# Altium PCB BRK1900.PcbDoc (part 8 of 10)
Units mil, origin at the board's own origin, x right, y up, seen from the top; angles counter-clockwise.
Board outline 8858.27 x 5905.51 mil, 10 copper layers (L1-TOP, L2-GND, L3-SIG1, L4-GND, L5-PWR, L6-PWR, L7-GND, L8-SIG2, L9-GND, L10-BOT), stack 48.824 mil thick; 507 components, 607 nets, 2498 pads, 2210 vias.
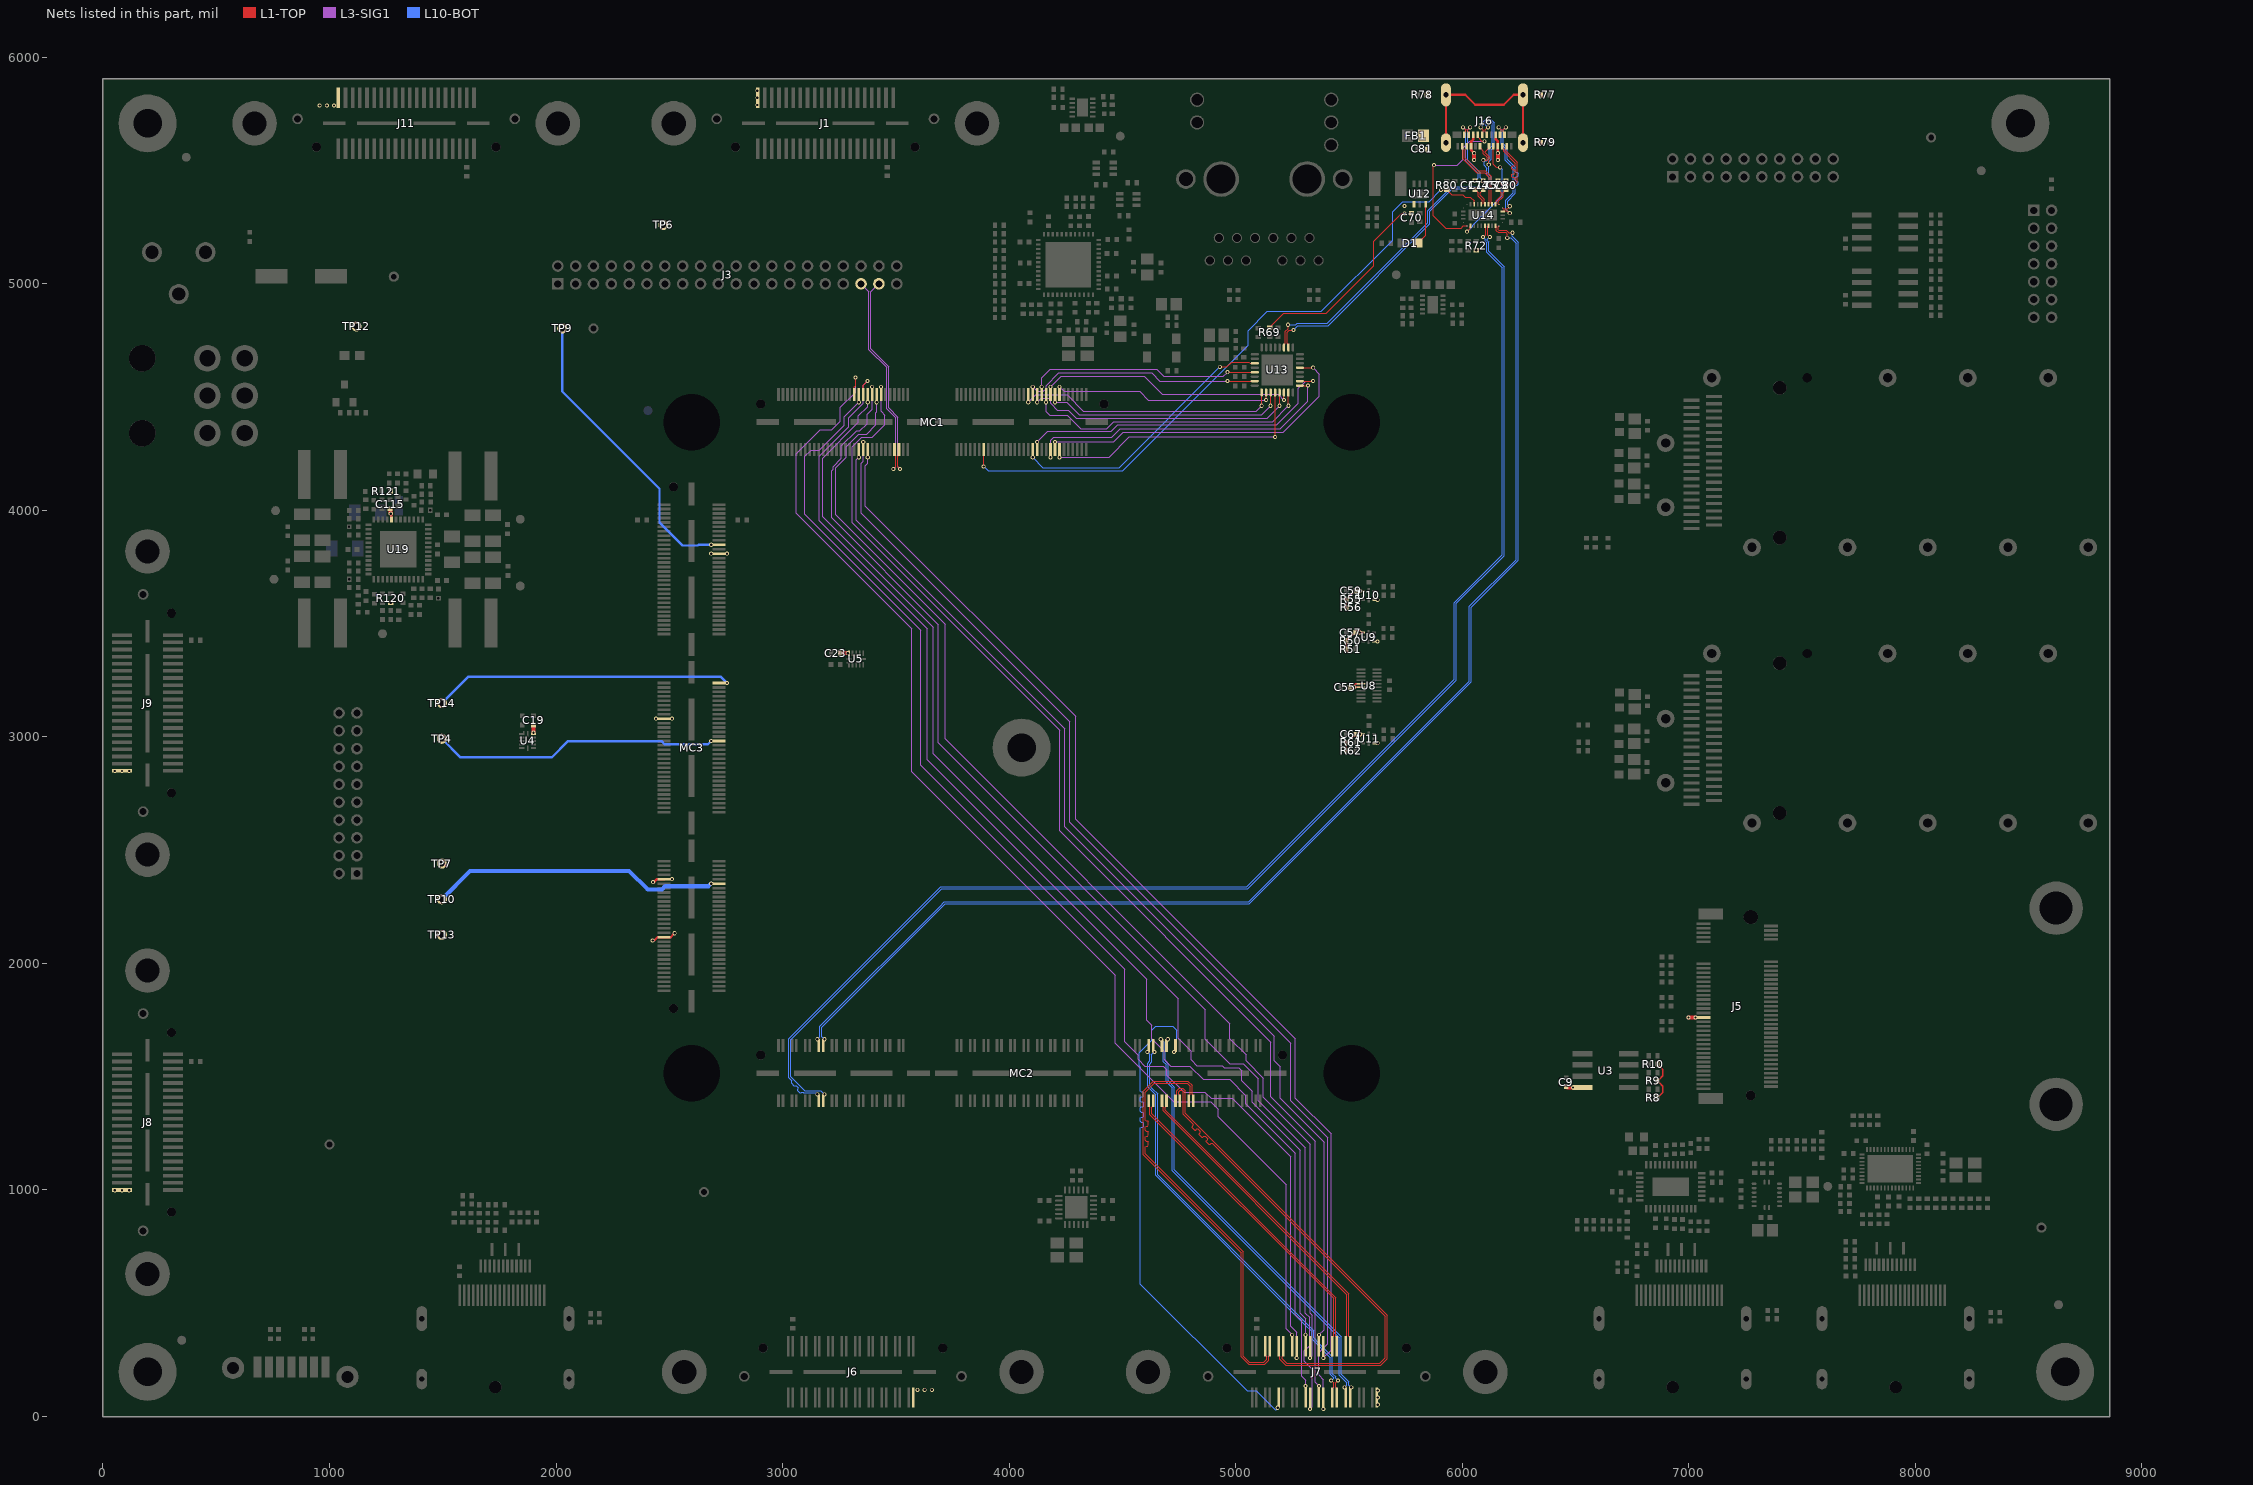
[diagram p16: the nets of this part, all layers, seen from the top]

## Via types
v1: diameter 18, hole 10, L1-TOP to L10-BOT, tented both sides, 2210 vias

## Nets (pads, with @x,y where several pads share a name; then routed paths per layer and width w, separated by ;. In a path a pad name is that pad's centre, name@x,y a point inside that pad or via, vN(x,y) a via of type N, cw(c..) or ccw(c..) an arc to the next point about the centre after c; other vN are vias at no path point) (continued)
SZG_PORTF_RX1P: J7.9 MC2.93 | length 2286.4
  L10-BOT w3.3: v1(4728.35,1609.4) 4739.59,1620.65 4739.59,1704.41 4722,1722 4646.56,1722 4630.06,1705.5 4630.06,1659.94 4575,1604.88 4575,1547.73 4580,1542.73 4580,1443 4580,1436.74 4583.35,1433.4 4589.27,1433.4 4592.61,1430.05 4592.61,1414.44 4589.27,1411.1 4583.35,1411.1 4580,1407.75 4580,1392.14 4583.35,1388.8 4590.66,1388.8 4594,1385.45 4594,1369.84 4590.66,1366.5 4583.35,1366.5 4580,1363.15 4580,1347.54 4583.35,1344.2 4590.66,1344.2 4594,1340.85 4594,1325.24 4590.66,1321.9 4583.35,1321.9 4580,1318.55 4580,1302.94 4583.35,1299.6 4590.66,1299.6 4594,1296.25 4594,1280.64 4590.66,1277.3 4583.35,1277.3 4580,1273.95 4580,1250 4580,584 5051,113 5092,113 5174,31 5178.71,31 v1@5186.56,38.86
  other v1: 5185.46,38.86
SZG_PORTF_RX2N: J7.31 MC2.91 | length 1880.8
  L10-BOT w3.3: v1(4700.79,1665.4) 4689.54,1654.15 4689.54,1570.46 4702,1558 4702,1482 4730,1454 4730,1089 5467,352 5467,185.85 5500.12,152.73 5500.12,138.14 v1@5509.4,128.86
  other v1: 5510.5,128.86
SZG_PORTF_RX2P: J7.29 MC2.89 | length 1880.8
  L10-BOT w3.3: v1(4669.29,1665.4) 4680.54,1654.15 4680.54,1566.73 4693,1554.27 4693,1478.27 4721,1450.27 4721,1085.27 5458,348.27 5458,182.12 5491.12,149 5491.12,138.14 v1@5481.84,128.86
  other v1: 5480.74,128.86
SZG_PORTF_RX3N: J7.27 MC2.87 | length 1884.5
  L1-TOP w3.3: J7.27@5446.41,83.86 5446.41,123.22 5441.06,128.57 5441.06,149.58 v1@5450.34,158.86
  L10-BOT w3.3: v1(4641.73,1609.4) 4630.48,1598.15 4630.48,1566.27 4620,1555.79 4620,1460 4633,1447 4656,1424 4656,1067.73 5306.73,417 5344,379.73 5344,347 5363,328 5427,264 5427,189.79 5441.06,175.73 5441.06,168.14 v1@5450.34,158.86
  other v1: 5451.44,158.86
SZG_PORTF_RX3P: J7.25 MC2.85 | length 1884.5
  L1-TOP w3.3: v1@5422.78,158.86 5432.06,149.58 5432.06,128.43 5426.72,123.09 J7.25@5426.72,83.86
  L10-BOT w3.3: v1(4610.24,1609.4) 4621.48,1598.15 4621.48,1570 4611,1559.52 4611,1456.27 4647,1420.27 4647,1064 5303,408 5335,376 5335,343.27 5418,260.27 5418,186.06 5432.06,172 5432.06,168.14 v1@5422.78,158.86
  other v1: 5421.68,158.86
SZG_PORTF_S0: J7.14 MC1.35 | length 5444.4
  L1-TOP w4.55: MC1.35@3316.93,4511.42 3316.93,4544.93 3322.07,4550.07 v1(3322.07,4586.36)
  L3-SIG1 w4.05: v1(3322.07,4586.36) 3322.07,4522.07 3254.64,4454.64 3254.64,4392.64 3217.54,4355.54 3165.92,4355.54 3060,4249.62 3060,3987 3570.5,3476.5 3570.5,2846.82 4468.5,1948.82 4468.5,1648.47 4726.98,1390 4891,1390 4924,1357 4924,1323.68 5224,1023.68 5224,386.4 v1(5249.56,360.84)
SZG_PORTF_S1: J7.16 MC1.37 | length 5393.9
  L3-SIG1 w4.05: v1(3336.61,4477.42) 3272,4412.8 3272,4375.72 3162.28,4266 3126,4266 3099,4239 3099,3983 3611,3471 3611,2874 4510.5,1974.5 4510.5,1653.5 4569.5,1594.5 4569.5,1576.5 4599,1547 4681,1547 4697,1531 4697,1507.5 4772.5,1432 4864,1432 4892,1404 4986,1404 5244,1146 5244,398.01 5269.24,372.77 v1(5269.24,258.84)
SZG_PORTF_S2: J7.17 MC1.39 | length 5599.6
  L1-TOP w4.55: MC1.39@3356.3,4511.42 3356.3,4552.63 v1(3375.31,4571.65)
  L3-SIG1 w4.05: v1(3375.31,4571.65) 3356.3,4552.63 3356.3,4472.3 3292,4408 3292,4369 3162,4239 3162,3954 3638.5,3477.5 3638.5,2899.5 4607,1931 4607,1749 4629,1727 4629,1668 4684,1613 4684,1577 4714,1547 4797,1547 4856,1488 4973,1488 5045,1416 5045,1381 5264,1162 5264,449 5291,422 5291,178 5308.61,160.39 v1(5308.61,134.86)
SZG_PORTF_S3: J7.18 MC1.41 | length 5185
  L3-SIG1 w4.05: v1(3375.98,4477.42) 3375.98,4457.98 3335,4417 3335,4388 3177,4230 3177,3973 3666,3484 3666,2925 4747,1844 4747,1670 4804,1613 4804,1574 4829,1549 4941,1549 4950,1540 5014,1540 5028,1526 5028,1483 5074,1437 5074,1388 5286,1176 5286,455 5308.61,432.39 v1(5308.61,360.84)
SZG_PORTF_S4: J7.19 MC1.43 | length 5532.5
  L3-SIG1 w4.05: v1(3395.67,4545.42) 3395.67,4446.67 3373,4424 3373,4383 3341,4351 3326.58,4351 3260,4284.42 3260,4229.08 3224,4193.08 3224,4181 3217,4174 3217,3967 3688,3496 3688,2974 4866,1796 4866,1665 4973,1558 5034,1558 5100,1492 5100,1395 5308,1187 5308,456 5326.17,437.83 5326.17,313.17 5303,290 5303,243 5338,208 5338,42.56 v1(5328.3,32.86)
SZG_PORTF_S5: J7.20 MC1.45 | length 5190.1
  L3-SIG1 w4.05: v1(3415.35,4477.42) 3415.35,4435.35 3412,4432 3412,4378 3371,4337 3336.23,4337 3281,4281.77 3281,4235.3 3234,4188.3 3234,3981 3718,3497 3718,2991 4975,1734 4975,1667 5046,1596 5046,1570 5122,1494 5122,1410 5330,1202 5330,455 5338.58,446.42 5338.58,269.12 v1(5328.3,258.84)
SZG_PORTF_S6: J7.21 MC1.47 | length 5358.7
  L3-SIG1 w4.05: v1(3435.04,4545.42) 3435.04,4436.96 3452,4420 3452,4379 3396,4323 3349.06,4323 3307,4280.94 3307,3945 4223,3029 4223,2585 5155,1653 5155,1550 5155,1412 5351,1216 5351,151.53 v1(5367.67,134.86)
SZG_PORTF_S7: J7.22 MC1.38 | length 4742.7
  L3-SIG1 w4.05: v1(3336.61,4234.11) 3326,4223.5 3326,3957 4246,3037 4246,2603 5170,1679 5170,1571 5196,1545 5196,1405 5391,1210 5391,384.18 v1(5367.67,360.84)
SZG_PORTF_S8: J7.23 MC1.40 | length 5151.4
  L3-SIG1 w4.05: v1(3356.3,4302.11) 3356.3,4216.3 3347,4207 3347,3988 4267,3068 4267,2623 5243,1647 5243,1394 5406,1231 5406,321 5366,281 5366,184 5387.35,162.65 v1(5387.35,32.86)
SZG_PORTF_S9: J7.24 MC1.42 | length 4844.5
  L3-SIG1 w4.05: v1(3375.98,4234.11) 3375.98,4206.98 3366,4197 3366,4019 4293.5,3091.5 4293.5,2636.5 5263,1667 5263,1406 5421,1248 5421,292.49 v1(5387.35,258.84)
SZG_PORTF_TX0N: J7.8 MC2.100 | length 1867.5
  L1-TOP w3.3: MC2.100@4812.99,1394.09 4812.99,1417.03 4807.65,1422.37 4807.65,1432.73 4807.65,1461.54 4789.5,1479.69 4635.96,1479.69 4610.06,1453.78 4592,1435.73 4592,1156 5025,723 5025,263.27 5057.27,231 5127.73,231 5145.79,249.06 5145.79,265.14 5151.13,270.48 J7.8@5151.13,309.84
SZG_PORTF_TX0P: J7.6 MC2.98 | length 1867.5
  L1-TOP w3.3: MC2.98@4793.31,1394.09 4793.31,1416.67 4798.65,1422.01 4798.65,1457.81 4785.77,1470.69 4639.69,1470.69 4601,1432 4601,1326 4601,1308 4604.35,1304.66 4611.24,1304.66 4614.58,1301.31 4614.58,1285.7 4611.24,1282.36 4604.35,1282.36 4601,1279.01 4601,1263.4 4604.35,1260.06 4611.66,1260.06 4615,1256.71 4615,1241.1 4611.66,1237.76 4604.35,1237.76 4601,1234.41 4601,1218.8 4604.35,1215.46 4611.66,1215.46 4615,1212.11 4615,1196.5 4611.66,1193.16 4604.35,1193.16 4601,1189.81 4601,1165.86 4601,1159.73 5034,726.73 5034,267 5061,240 5124,240 5136.79,252.79 5136.79,264.74 5131.45,270.09 J7.6@5131.45,309.84
SZG_PORTF_TX1N: J7.12 MC2.96 | length 2202.8
  L1-TOP w3.3: MC2.96@4753.94,1394.09 4753.94,1416.88 4748.59,1422.22 4748.59,1434.59 4755,1441 4763,1441 4769,1435 4769,1334 4796,1307 4812.94,1290.06 4812.94,1285.33 4807.77,1280.17 4807.77,1275.43 4818.8,1264.4 4823.54,1264.4 4828.7,1269.57 4833.43,1269.57 4844.47,1258.53 4844.47,1253.8 4839.3,1248.63 4839.3,1243.9 4850.34,1232.86 4855.07,1232.86 4860.24,1238.03 4864.97,1238.03 4876.01,1226.99 4876.01,1222.26 4871.14,1217.39 4871.14,1212.66 4882.18,1201.62 4886.91,1201.62 4891.78,1206.49 4896.51,1206.49 4905,1198 5660,443 5660,259 5636,235 5225.84,235 5204.84,256 5204.84,264.72 5210.19,270.06 J7.12@5210.19,309.84
SZG_PORTF_TX1P: J7.10 MC2.94 | length 2202.8
  L1-TOP w3.3: MC2.94@4734.25,1394.09 4734.25,1416.66 4739.59,1422 4739.59,1438.32 4751.27,1450 4766.73,1450 4778,1438.73 4778,1337.73 5669,446.73 5669,255.27 5639.73,226 5222.12,226 5195.84,252.27 5195.84,265.46 5190.5,270.8 J7.10@5190.5,309.84
SZG_PORTF_TX2N: J7.32 MC2.92 | length 1424.4
  L1-TOP w3.3: MC2.92@4694.88,1394.09 4694.88,1371.18 4689.54,1365.84 4689.54,1352.46 4714,1328 5500.12,541.88 5500.12,354.26 5505.46,348.92 J7.32@5505.46,309.84
SZG_PORTF_TX2P: J7.30 MC2.90 | length 1424.4
  L1-TOP w3.3: MC2.90@4675.2,1394.09 4675.2,1371.09 4680.54,1365.75 4680.54,1348.73 5491.12,538.15 5491.12,354.2 5485.78,348.86 J7.30@5485.78,309.84
SZG_PORTF_TX3N: J7.28 MC2.88 | length 1424.4
  L1-TOP w3.3: MC2.88@4635.83,1394.09 4635.83,1371.34 4630.48,1366 4630.48,1335.52 5441.06,524.94 5441.06,354.03 5446.41,348.69 J7.28@5446.41,309.84
SZG_PORTF_TX3P: J7.26 MC2.86 | length 1424.4
  L1-TOP w3.3: MC2.86@4616.14,1394.09 4616.14,1371.26 4621.48,1365.91 4621.48,1331.79 5432.06,521.21 5432.06,354.59 5426.72,349.25 J7.26@5426.72,309.84
USB_CC1: J16.A5 U14.2 | length 509.1
  L1-TOP w5: v1(6021.41,5230.32) 6035.82,5244.74 6035.82,5254.56 U14.2@6037.26,5256 ; J16.A5@6137.8,5607.09 6137.8,5528.7 6148.6,5517.9 6152.25,5514.25 v1(6167.86,5514.25)
  L10-BOT w5: v1(6021.41,5230.32) 6046,5254.91 6046,5259 6176,5389 6176,5505.58 6168.03,5513.55 6163.68,5517.9 6167.33,5514.25 v1(6167.86,5514.25)
USB_CC2: J16.B5 U14.1 | length 743.3
  L1-TOP w5: v1(5876,5524) 5872.61,5520.61 5872.61,5300.39 5927.01,5245.99 5995.08,5245.99 6005.09,5256 U14.1@6021.51,5256 ; J16.B5@6068.9,5658.27 6068.9,5648.32 6087.37,5629.85 6097.71,5629.85 v1(6098.46,5629.1)
  L3-SIG1 w5: v1(5876,5524) 5979,5524 6003,5548 6003,5598 6034.1,5629.1 v1(6098.46,5629.1)
USB_CLKOUT: MC1.93 U13.1 | length 1142.6
  L1-TOP w4.55: v1(5115.05,4461.87) U13.1@5115.05,4520.65
  L3-SIG1 w4.05: v1(4084.65,4477.42) 4117.15,4509.92 4256.08,4509.92 4328.29,4437.71 5090.89,4437.71 v1(5115.05,4461.87)
USB_DATA0: MC1.105 U13.3 | length 1049.5
  L1-TOP w4.55: v1(5154.41,4461.87) U13.3@5154.42,4520.65
  L3-SIG1 w4.05: v1(4202.76,4477.42) 4254.58,4477.42 4309.53,4422.47 5115.01,4422.47 v1(5154.41,4461.87)
USB_DATA1: MC1.108 U13.4 | length 1185.9
  L1-TOP w4.55: U13.4@5174.1,4520.65 5174.1,4324.68 v1(5174.47,4324.31)
  L3-SIG1 w4.05: v1(4222.44,4234.11) 4441.11,4234.11 4531.31,4324.31 v1(5174.47,4324.31)
USB_DATA2: MC1.97 U13.5 | length 1202.4
  L1-TOP w4.55: v1(5193.79,4461.87) U13.5@5193.79,4520.65
  L3-SIG1 w4.05: v1(4124.02,4477.42) 4141.4,4494.8 4174.76,4494.8 4183,4486.56 4183,4472.64 4212.64,4443 4261,4443 4296.3,4407.7 5139.62,4407.7 v1(5193.79,4461.87)
USB_DATA3: MC1.103 U13.6 | length 1127
  L1-TOP w4.55: v1(5213.47,4486.87) U13.6@5213.47,4520.65
  L3-SIG1 w4.05: v1(4183.07,4545.42) 4229.65,4592 4597,4592 4677,4512 5188.34,4512 v1(5213.47,4486.87)
USB_DATA4: MC1.101 U13.7 | length 1244.5
  L1-TOP w4.55: v1(5233.16,4461.87) U13.7@5233.16,4520.65
  L3-SIG1 w4.05: v1(4163.39,4477.42) 4163.39,4434.6 4178.99,4419 4257,4419 4316,4360 4431,4360 4463,4392 5163.29,4392 v1(5233.16,4461.87)
USB_DATA5: MC1.104 U13.9 | length 1388.3
  L1-TOP w4.55: U13.9@5283.35,4551.16 5318.57,4551.16 v1(5319.13,4551.72)
  L3-SIG1 w4.05: v1(4183.07,4234.11) 4183.07,4309.07 4196.43,4322.43 4453,4322.43 4491.57,4361 5198,4361 5319.13,4482.13 v1(5319.13,4551.72)
USB_DATA6: MC1.98 U13.10 | length 1427.5
  L1-TOP w4.55: U13.10@5283.35,4570.84 v1(5342.13,4570.84)
  L3-SIG1 w4.05: v1(4124.02,4302.11) 4170.9,4349 4451,4349 4479,4377 5182,4377 5277,4472 5277,4539 5308.84,4570.84 v1(5342.13,4570.84)
USB_DATA7: MC1.106 U13.13 | length 1447.2
  L1-TOP w4.55: U13.13@5283.35,4629.9 v1(5342.13,4629.9)
  L3-SIG1 w4.05: v1(4202.76,4302.11) 4463,4302.11 4504.89,4344 5210.14,4344 5370.08,4503.94 5370.08,4601.95 v1(5342.13,4629.9)
USB_DIR: MC1.95 U13.31 | length 1043.8
  L1-TOP w4.55: v1(4964.54,4570.84) U13.31@5084.54,4570.84
  L3-SIG1 w4.05: v1(4104.33,4545.42) 4123.75,4526 4151,4526 4163,4538 4163,4550 4220,4607 4629,4607 4665.16,4570.84 v1(4964.54,4570.84)
USB_DN: J16.A7 J16.B7 U13.19 | length 1777.1
  L1-TOP w4.05: U13.19@5213.47,4719.46 5213.47,4731.27 5218.81,4736.61 5218.81,4789.8 5231.38,4802.36 v1(5231.38,4819.62) ; J16.A7@6078.74,5607.09 6078.74,5599.99 6093.93,5584.81 6093.93,5574.08 6108,5560 6111.51,5556.49 6111.51,5548.49 6109.11,5546.1 v1(6093.48,5546.1) ; J16.B7@6108.27,5658.27 6108.27,5666.12 6102.93,5671.46 6102.93,5679.55 v1(6114.41,5691.04)
  L10-BOT w4.05: v1(5231.38,4819.62) 5265.59,4819.62 5270.97,4825 5405,4825 5849,5269 5849,5307.08 5849,5323.45 5953.55,5428 6106,5428 6120,5442 6120,5469.33 6108.48,5480.86 6108.48,5510.79 6096.48,5522.79 6096.48,5543.1 6109.11,5543.1 6119.5,5553.49 6119.5,5596.5 6133,5610 6133,5708 6123.52,5717.48 6108.95,5717.48 6102.48,5711 6102.48,5702.98 v1(6114.41,5691.04)
USB_DP: J16.A6 J16.B6 U13.18 | length 1784.5
  L1-TOP w4.05: U13.18@5233.16,4719.46 5233.16,4731.49 5227.81,4736.83 5227.81,4786.07 5237.74,4796 v1(5255,4796) ; v1(6081.54,5691.04) 6093.93,5678.66 6093.93,5671.26 6088.58,5665.91 J16.B6@6088.58,5658.27 ; v1(6117.48,5526.1) 6117.48,5541.74 6117.87,5542.13 6120.51,5544.77 6120.51,5560.22 6117.87,5562.86 6102.93,5577.8 6102.93,5584.15 6118.11,5599.33 J16.A6@6118.11,5607.09
  L10-BOT w4.05: v1(5255,4796) 5275,4816 5408.73,4816 5858,5265.27 5858,5319.72 5957.28,5419 6109.73,5419 6112.36,5421.64 6129,5438.27 6129,5473.06 6117.48,5484.58 v1(6117.48,5526.1) 6117.48,5538.74 6128.5,5549.76 6128.5,5592.77 6142,5606.27 6142,5711.73 6127.25,5726.48 6105.23,5726.48 6093.48,5714.73 6093.48,5702.98 v1(6081.54,5691.04)
USB_NXT: MC1.107 U13.2 | length 970.3
  L1-TOP w4.55: v1(5134.73,4486.87) U13.2@5134.73,4520.65
  L3-SIG1 w4.05: v1(4222.44,4545.42) 4242.86,4525 4279.98,4525 4577,4525 4615.13,4486.87 v1(5134.73,4486.87)
USB_RESET_B: MC1.96 U13.27 | length 1194.2
  L1-TOP w4.55: v1(4930.11,4633.87) 4961.87,4633.87 4983,4655 5059,4655 5064.42,4649.58 U13.27@5084.54,4649.58
  L10-BOT w4.55: v1(4104.33,4234.11) 4149.44,4189 4485.23,4189 v1(4930.11,4633.87)
USB_SHELL: C81.2 FB1.1 J16.M1 J16.M2 J16.M3 J16.M4 R77.1 R78.1 R79.1 | length 798.8
  L1-TOP w10: J16.M2@5928.35,5623.23 J16.M3@5928.35,5834.25 6013.08,5834.25 6057.23,5790.1 6183.55,5790.1 6227.7,5834.25 J16.M4@6268.5,5834.25 J16.M1@6268.5,5623.23
USB_SSRX_N: MC2.15 U14.10 | length 5720.4
  L1-TOP w4.05: U14.10@6163.24,5256 6159.87,5252.63 6159.87,5239 6162.87,5236 6195.05,5236 6203.02,5228.02 6205.36,5225.68 v1(6221.69,5225.68)
  L10-BOT w4.05: v1(3185.04,1665.4) 3173.79,1676.65 3173.79,1719 3718.57,2263.78 5060.84,2263.78 6040,3242.94 6040,3572.27 6247,3779.27 6247,5184.05 6221.69,5209.36 v1(6221.69,5225.68)
USB_SSRX_P: MC2.13 U14.9 | length 5720.4
  L1-TOP w4.05: U14.9@6147.5,5256 6150.87,5252.63 6150.87,5235.27 6159.14,5227 6191.32,5227 6199,5219.32 v1(6199,5203)
  L10-BOT w4.05: v1(3153.54,1665.4) 3164.79,1676.65 3164.79,1722.73 3695.06,2253 3714.84,2272.78 5057.11,2272.78 6031,3246.67 6031,3576 6238,3783 6238,5180.32 6215.32,5203 v1(6199,5203)
USB_SSRXN1: J16.B10 U14.14 | length 503.9
  L1-TOP w4.05: v1(6161.02,5691.04) 6172.67,5679.4 6172.67,5671.67 6167.32,5666.33 J16.B10@6167.32,5658.27 ; U14.14@6178.99,5318.99 6182.37,5322.37 6199.77,5322.37 v1(6210.05,5312.09)
  L10-BOT w4.05: v1(6161.02,5691.04) 6172.46,5679.6 6172.46,5615.81 6190.64,5597.64 6190.64,5546.36 6226,5511 6226,5402.73 6192,5368.73 6192,5330.14 v1(6210.05,5312.09)
USB_SSRXN2: J16.A10 U14.18 | length 327.7
  L1-TOP w4.05: J16.A10@6019.69,5607.09 6019.69,5598.83 6014.34,5593.49 6014.34,5553.66 6067.96,5500.04 6102.52,5500.04 6128.37,5474.19 6128.37,5353.86 U14.18@6131.75,5350.49
USB_SSRXP1: J16.B11 U14.15 | length 501.8
  L1-TOP w4.05: U14.15@6178.99,5334.74 6182.37,5331.37 6201.76,5331.37 v1@6210.05,5339.65 ; J16.B11@6187.01,5658.27 6187.01,5666.25 6181.67,5671.6 6181.67,5679.81 v1(6192.89,5691.04)
  L10-BOT w4.05: v1(6192.89,5691.04) 6181.46,5679.6 6181.46,5619.54 6197,5604 6199.64,5601.36 6199.64,5550.09 6235,5514.73 6235,5502 6235,5495.85 6238.81,5492.04 6243.19,5492.04 6247,5488.23 6247,5476.8 6243.19,5472.99 6238.81,5472.99 6235,5469.18 6235,5457.75 6238.81,5453.94 6243.19,5453.94 6247,5450.13 6247,5438.7 6243.19,5434.89 6238.81,5434.89 6235,5431.08 6235,5410 6235,5399 6201,5365 6201,5348.69 v1@6210.05,5339.65
  other v1: 6210.05,5342.65
USB_SSRXP2: J16.A11 U14.19 | length 327.7
  L1-TOP w4.05: J16.A11@6000,5607.09 6000,5598.96 6005.34,5593.62 6005.34,5549.93 6055.27,5500 6064.23,5491.04 6098.79,5491.04 6119.37,5470.46 6119.37,5353.86 U14.19@6116,5350.49
USB_SSTX_N: MC2.16 U14.7 | length 6072.5
  L1-TOP w4.05: U14.7@6116,5256 6112.63,5252.63 6112.63,5215.37 v1@6121,5207
  L10-BOT w4.05: v1(3185.04,1422.09) 3169.56,1437.58 3097.42,1437.58 3036,1499 3036,1664 3702,2330 5052.72,2330 5973.98,3251.27 5973.98,3589.26 6185,3800.27 6185,5075 6117,5143 6117,5185.72 6111.72,5191 6111.72,5197.72 v1@6121,5207
  other v1: 6122.1,5207
USB_SSTX_P: MC2.14 U14.6 | length 6072.5
  L1-TOP w4.05: v1@6093.44,5207 6103.63,5217.19 6103.63,5252.63 U14.6@6100.25,5256
  L10-BOT w4.05: v1(3153.54,1422.09) 3147.06,1428.58 3093.7,1428.58 3092.27,1430 3090.84,1431.43 3084.89,1431.43 3082.9,1429.45 3076.95,1429.45 3068.02,1438.38 3068.02,1444.33 3070,1446.32 3070,1452.27 3061.07,1461.2 3055.12,1461.2 3049.16,1461.2 3040.23,1470.13 3040.23,1476.09 3040.23,1482.04 3036.64,1485.64 3027,1495.27 3027,1667.73 3698.27,2339 5048.99,2339 5964.98,3255 5964.98,3592.98 6176,3804 6176,5071.27 6110,5137.27 6108,5139.27 6108,5181.99 6102.72,5187.27 6102.72,5197.72 v1@6093.44,5207
  other v1: 6092.34,5207
USB_SSTXN1: C80.2 J16.A3 | length 270.8
  L1-TOP w4.05: J16.A3@6177.17,5607.09 6177.17,5598.97 6182.51,5593.63 6182.51,5584.49 6234.78,5532.22 6234.78,5524.32 6231.37,5520.91 6223.26,5520.91 6219.85,5517.5 6219.85,5507.27 6223.26,5503.86 6231.37,5503.86 6234.78,5500.45 6234.78,5490.22 6231.37,5486.81 6222.19,5486.81 6218.78,5483.4 6218.78,5473.17 6222.19,5469.76 6231.37,5469.76 6234.78,5466.35 6234.78,5464.33 6234.78,5452.5 6229.29,5447 6202.08,5447 v1(6194,5455.08)
USB_SSTXN1_C: C80.1 U14.16 | length 80
  L1-TOP w4.05: U14.16@6163.24,5350.49 6159.87,5353.86 6159.87,5364 6180.5,5384.63 6180.5,5401.42 C80.1@6194,5414.92
USB_SSTXN2: C175.2 J16.B3 | length 308.9
  L1-TOP w4.05: J16.B3@6029.53,5658.27 6029.53,5666.37 6024.19,5671.71 6024.19,5679.81 v1(6035.41,5691.04)
  L10-BOT w4.05: v1(6035.41,5691.04) 6023.98,5679.6 6023.98,5545.33 6079.5,5489.81 6079.5,5468.58 v1(6093,5455.08)
USB_SSTXN2_C: C175.1 U14.20 | length 78.6
  L1-TOP w4.05: C175.1@6093,5414.92 6079.5,5401.42 6079.5,5390.89 6096.88,5373.51 6096.88,5369.73 6096.88,5353.86 U14.20@6100.25,5350.49
USB_SSTXP1: C79.2 J16.A2 | length 279.5
  L1-TOP w4.05: v1(6158,5455.08) 6175.08,5438 6223.73,5438 6233.02,5438 6243.78,5448.77 6243.78,5458.06 6243.78,5530.94 6243.78,5535.94 6191.51,5588.22 6191.51,5593.39 6196.85,5598.73 J16.A2@6196.85,5607.09
USB_SSTXP1_C: C79.1 U14.17 | length 80
  L1-TOP w4.05: U14.17@6147.5,5350.49 6150.87,5353.86 6150.87,5367.73 6171.5,5388.36 6171.5,5401.42 C79.1@6158,5414.92
USB_SSTXP2: C174.2 J16.B2 | length 309.1
  L1-TOP w4.05: v1(6003.54,5691.04) 6015.19,5679.4 6015.19,5671.84 6009.84,5666.49 J16.B2@6009.84,5658.27
  L10-BOT w4.05: v1(6003.54,5691.04) 6014.98,5679.6 6014.98,5545.29 6014.98,5541.6 6070.5,5486.08 6070.5,5468.58 v1(6057,5455.08)
USB_SSTXP2_R: C174.1 U14.21 | length 78.6
  L1-TOP w4.05: C174.1@6057,5414.92 6070.5,5401.42 6070.5,5387.16 6087.88,5369.78 6087.88,5353.86 U14.21@6084.5,5350.49
USB_STP: MC1.99 U13.29 | length 1015.5
  L1-TOP w4.55: v1(4964.54,4610.21) U13.29@5084.54,4610.21
  L3-SIG1 w4.05: v1(4143.7,4545.42) 4143.7,4584.7 4181,4622 4652.21,4622 4682.21,4592 4946.32,4592 v1(4964.54,4610.21)
USB_TYPEC_INT_B: MC1.74 R80.1 U14.23 | length 2908.4
  L1-TOP w5: v1(3887.79,4194.11) MC1.74@3887.79,4268.11 ; v1(5906.68,5414.4) 5931.64,5414.4 5953.05,5393 6003.25,5393 6013,5383.25 6036.75,5383.25 6053.01,5366.99 U14.23@6053.01,5350.49
  L10-BOT w5: v1(3887.79,4194.11) 3906.91,4175 4502,4175 5055,4728 5055,4793 5140,4878 5378,4878 5693,5193 5693,5318.85 5737.15,5363 5855,5363 5906.4,5414.4 v1(5906.68,5414.4)
USB_VBUS: C70.2 J16.A4 J16.A9 J16.B4 J16.B9 R69.1 R72.2 U12.1 | length 1104.3
  L1-TOP w5: R69.1@5150.41,4805.55 5150.41,4807.41 5213,4870 5399,4870 5609,5080 5609,5187 5733.04,5311.04 v1(5745.54,5311.04)
  L1-TOP w11: J16.B4@6049.21,5658.27 6049.21,5638.48 6039.37,5628.64 J16.A9@6039.37,5607.09 6039.37,5590.55 v1(6052.82,5577.1) ; J16.B9@6147.64,5658.27 6147.64,5638.94 6157.48,5629.1 J16.A4@6157.48,5607.09 v1(6157.48,5577.1)
  L1-TOP w18: v1(6052.82,5547.1) v1(6052.82,5577.1) ; v1(6157.48,5547.1) v1(6157.48,5577.1)
  other v1: 6062.41,5148.64 5777.06,5311.04 5745.23,5343.37
VBUS_FAULT: D1.1 U12.3 | length 186.3
  L1-TOP w5: D1.1@5803.46,5180 5838.59,5215.13 U12.3@5838.59,5351.72
VCC_EEPROM_FPX1301: C9.2 J5.33 R8.2 R9.2 R10.2 U3.8 | length 295.4
  L1-TOP w7: v1(6862.28,1407.15) 6862.28,1409.12 6868.63,1415.46 6870.59,1415.46 6885.6,1430.46 6885.6,1457.83 6870.59,1472.84 6868.63,1472.84 6862.28,1479.18 R9.2@6862.28,1481.15 6862.28,1483.12 6868.63,1489.46 6870.59,1489.46 6885.6,1504.46 6885.6,1531.83 6870.59,1546.84 6868.63,1546.84 6862.28,1553.18 R10.2@6862.28,1555.15
  L1-TOP w18: C9.2@6459.6,1456.07 6460.19,1456.07 6464.11,1452.15 v1(6489.24,1452.15) U3.8@6531.24,1452.15 ; v1(6999,1761.81) v1(7029.94,1761.81)
VCC_PSBATT: MC3.120 TP14.1 | length 1317.9
  L10-BOT w11: TP14.1@1496.06,3149.61 1611.46,3265 2728.27,3265 v1(2755.08,3238.19)
VCCO_28: J1.39 J7.39 MC3.158 TP6.1
  other v1: 5627.57,52.36 5627.57,83.86 5627.57,115.35 2685.08,3809.06 2755.08,3809.06 2888.58,5789.97 2888.58,5821.46 2888.58,5852.96
VCCO_67: C23.2 J6.39 J11.39 MC3.103 TP12.1 U5.11 | length 34.2
  L1-TOP w18: C23.2@3254.08,3370 C23.2@3254.45,3369.62 v1(3288.1,3369.62)
  other v1: 3596,118 3627.5,118 3659,118 2441.77,3080.71 2511.77,3080.71 956.71,5787.32 988.21,5787.32 1019.71,5787.32
VCCO_68: C19.2 J9.39 MC3.51 TP7.1 U4.11 | length 88.5
  L1-TOP w11: v1(2428.01,2358.73) 2432.73,2358.73 2446.05,2372.05 MC3.51@2476.77,2372.05
  L1-TOP w18: v1(1900.62,3018.9) 1900.62,3052.55 C19.2@1901,3052.92
  other v1: 2511.77,2372.05 52.55,2849.21 84.05,2849.21 115.55,2849.21
VCCO_87_88: C55.2 C57.2 C59.2 C67.2 J8.39 MC3.25 R50.2 R51.2 R55.2 R56.2 R61.2 R62.2 TP13.1 U8.5 U8.6 U9.1 U9.5 U10.1 U10.5 U11.1 U11.5 | length 534.8
  L1-TOP w5: R51.2@5488.77,3387.65 R50.2@5488.77,3424.65 5507.77,3443.65 5511.54,3443.65 C57.2@5528.54,3460.65 C57.2@5528.57,3460.68 ; R62.2@5489.77,2938.65 R61.2@5489.77,2975.65 5508.77,2994.65 5512.54,2994.65 C67.2@5529.54,3011.65 C67.2@5529.57,3011.68 ; R56.2@5489.77,3571.65 R55.2@5489.77,3608.65 5508.77,3627.65 5512.54,3627.65 C59.2@5529.54,3644.65 C59.2@5529.57,3644.68
  L1-TOP w7.5: U8.6@5552.57,3219.13 v1(5522.57,3219.13) 5522.57,3228.57 5528.87,3234.87 U8.5@5552.57,3234.87
  L1-TOP w10: v1(2426.79,2101.45) 2433.45,2101.45 2448.14,2116.14 MC3.25@2476.77,2116.14 2506.14,2116.14 2519.88,2129.88 2523.45,2133.45 v1(2523.74,2133.45)
  L1-TOP w18: C55.2@5504.08,3219 5504.2,3219.13 v1(5522.57,3219.13) ; C57.2@5528.57,3460.68 v1(5548.18,3460.68) ; C67.2@5529.57,3011.68 v1(5549.18,3011.68) ; C59.2@5529.57,3644.68 v1(5549.18,3644.68)
  other v1: 52.55,998.81 84.05,998.81 115.55,998.81 5626.82,2972.32 5625.82,3421.32 5626.82,3605.32
VDDD: C115.2 R120.2 R121.2 U19.20 | length 51.1
  L1-TOP w11: v1(1270.58,3985.64) 1270.58,3983.74 1273.65,3980.68 1273.65,3959.93 U19.20@1274.06,3959.53
  L1-TOP w18: C115.2@1267.58,4007.56 1268.17,4007.56 1269.41,4006.32 1269.41,3986.81 v1(1270.58,3985.64)
  other v1: 1270.29,3591.84 1269.98,4084.53
VREF_28: MC3.162 TP9.1 | length 1306.4
  L10-BOT w10: TP9.1@2027.56,4803.15 2027.56,4524.44 2456.43,4095.57 2456.43,3946.57 2558,3845 2625,3845 2628.43,3848.43 v1(2685.08,3848.43)
VREF_67: MC3.94 TP4.1 | length 1263.7
  L10-BOT w11: TP4.1@1496.06,2992.13 1578.19,2910 1981,2910 2051,2980 2467,2980 2480,2967 2669.79,2967 v1(2685.08,2982.28)
VREF_68: MC3.50 TP10.1 | length 1285.5
  L10-BOT w18: TP10.1@1496.06,2283.46 1620.6,2408 2323,2408 2405,2326 2467,2326 2482,2341 2673.72,2341 v1(2685.08,2352.36)
XADC_VN: J3.37 MC1.56 | length 975.2
  L1-TOP w3.3: MC1.56@3513.78,4268.11 3510.2,4264.53 3510.2,4241.56 3508.44,4239.8 3508.44,4192.39 v1@3517.72,4183.11
  L3-SIG1 w3.15: J3.37@3425.2,5000 3390.33,4965.13 3390.33,4712.67 3468,4635 3468,4452 3508.44,4411.56 3508.44,4192.39 v1@3517.72,4183.11
  other v1: 3518.82,4183.11
XADC_VP: J3.35 MC1.54 | length 975.2
  L1-TOP w3.3: v1@3490.16,4183.11 3499.44,4192.39 3499.44,4240.16 3494.09,4245.5 MC1.54@3494.09,4268.11
  L3-SIG1 w3.15: J3.35@3346.46,5000 3381.33,4965.13 3381.33,4708.95 3459,4631.27 3459,4448.27 3499.44,4407.84 3499.44,4192.39 v1@3490.16,4183.11
  other v1: 3489.06,4183.11
pads on no net: FID1.FID? FID2.FID? FID3.FID? FID4.FID? FID5.FID? FID6.FID? FID7.FID? FID8.FID? J1.37 J1.38 J1.MH J2.12 J5.2 J5.3 J5.4 J5.5 J5.6 J5.7 J5.9 J5.10 J5.12 J5.13 J5.14 J5.15 J5.16 J5.17 J5.19 J5.20 J5.22 J5.23 J5.24 J5.25 J5.26 J5.27 J5.30 J5.32 J5.34 J5.38 J5.40 J5.44 J5.46 J5.50 J5.52 J5.56 J5.58 J5.MH J6.37 J6.38 J6.MH J7.37 J7.38 J7.MH J8.37 J8.38 J8.MH J9.37 J9.38 J9.MH J11.37 J11.38 J11.MH J12.MH J13.1 J13.3 J13.4 J13.6 J13.M1 J14.MH J15.MH J16.A8 J16.B8 J17.13 J17.14 J18.3 J19.0 J20.7 J20.9 J20.10 J20.12 J20.M1 J21.7 J21.9 J21.10 J21.12 J21.M1 JSO1.1 JSO2.1 JSO3.1 JSO4.1 MC1.14 MC1.21 MC1.28 MC1.49 MC1.51 MC1.52 MC1.110 MC1.MH MC2.2 MC2.4 MC2.5 MC2.6 MC2.7 MC2.8 MC2.9 MC2.11 MC2.21 MC2.23 MC2.25 MC2.27 MC2.29 MC2.31 MC2.MH MC3.48 MC3.49 MC3.101 MC3.104 MC3.106 MC3.155 MC3.156 MC3.159 MC3.160 MC3.161 MC3.163 MC3.164 MC3.165 MC3.167 MC3.169 MC3.170 MC3.MH MH1.1 MH2.1 MH3.1 MH4.1 MH5.1 MH6.1 MH7.1 MH8.1 MH9.1 MH10.1 MH11.1 MH12.1 MH13.1 MH14.1 MH15.1 MH16.1 MH17.1 QSFP1.0 QSFP2.0 U2.5 U2.6 U2.8 U4.5 U4.7 U5.3 U5.4 U5.5 U5.7 U5.8 U5.9 U6.4 U6.11 U6.12 U6.27 U6.28 U6.31 U6.40 U6.41 U6.43 U6.44 U7.3 U7.14 U13.12 U13.15 U13.16 U14.24 U15.7 U16.43 U19.13 U19.27 U19.34 U19.41 U19.44 U19.48 U22.1 U22.6 U22.15 U22.16 U24.3 U24.14 U25.8 U25.9 U25.11 U25.12 U25.20 U25.21 U25.23 U25.24 U26.3 U26.14 Y2.2 Y2.4 Y3.2 Y3.4 Y4.2 Y4.4

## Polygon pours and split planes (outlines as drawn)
VCC_EEPROM_FPX1301 on L8-SIG2 "L8_VCC_EEPROM_FPX1301" (solid, pour order 134): 7185.04,1811.02 7185.04,1358.27 6397.64,1358.27 6397.64,1811.02
VDDD on L8-SIG2 "L8_VDDD" (solid, pour order 139): 1299.21,4074.8 1299.21,3562.99 1003.94,3562.99 1003.94,4114.17 1259.84,4114.17
VCCO_28 on L8-SIG2 "L8_VCCO_28" (solid, pour order 129): 6338.58,39.37 6338.58,1811.02 5374.02,2775.59 5374.02,5866.14 2283.46,5866.14 2283.46,3779.53 3937.01,3779.53 3937.01,1089 4501.55,1089 4970.28,620.28 4970.28,281 5211.91,39.37
DGND on L8-SIG2 "L8_DGND_3" (solid, pour order 145): 1358.27,3179 1079,3179 1079,2543 903,2543 257.02,3188.98 19.68,3188.98 19.68,5885.83 767.72,5885.83 767.72,4527.56 944.88,4350.39 944.88,3523.62 1358.27,3523.62
DGND on L8-SIG2 "L8_DGND_4" (solid, pour order 146): 3956.69,118.11 3956.69,944.88 4409.45,944.88 4842.52,511.81 4842.52,118.11
VCCO_67 on L8-SIG2 "L8_VCCO_67" (solid, pour order 130): 3897.64,107 3897.64,1240.16 3897.64,3740.16 2244.09,3740.16 2244.09,5802 885.83,5802 885.83,4616.17 1403,4099 1403,3110.24 1887.76,3110.24 1926,3072 2860,3072 2860,107
DISPLAYPORT_PL_SRC_VCC on L8-SIG2 "L8_DISPLAYPORT_PL_SRC_VCC" (solid, pour order 135): 6633.86,1279.53 6633.86,807.09 7204.72,807.09 7204.72,1279.53
DGND on L8-SIG2 "L8_DGND_1" (solid, pour order 140): 8838.58,5885.83 8838.58,39.37 6377.95,39.37 6377.95,1830.71 5413.39,2795.28 5413.39,5885.83
DGND on L8-SIG2 "L8_DGND_2" (solid, pour order 144): 19.68,19.68 19.69,2633 446,2633 953.02,2125.98 1614.17,2125.98 1828.29,2340.1 2814.96,2340.1 2814.96,19.68
DGND on L7-GND "L7_DGND" (solid, pour order 127): 19.68,19.68 19.68,5885.83 8838.58,5885.83 8838.58,19.68
AVDDL_KSZ9031 on L3-SIG1 "L3_AVDDL_KSZ9031" (solid, pour order 124): 4389.76,5157.48 4389.76,5019.68 4586.61,5019.68 4586.61,5157.48
AVDDL_PLL_KSZ9031 on L3-SIG1 "L3_AVDDL_PLL_KSZ9031" (solid, pour order 121): 4468.5,4743 4468.5,4960.63 4232.28,4960.63 4232.28,4743
+1.2V_DP on L3-SIG1 "L3_+1.2V_DP" (solid, pour order 117): 7534,1096 7534,853 8212,853 8212,1377.95 7647,1377.95 7647,1209
VCCO_68 on L3-SIG1 "L3_VCCO_68" (solid, pour order 131): 2531,2637.8 2531,2271 2192.26,2271 1496.06,1574.8 39.37,1574.8 39.37,3044 1968,3044 2374.2,2637.8
+1.2V_ETH on L3-SIG1 "L3_+1.2V_ETH" (solid, pour order 118): 3679,5742 4803.15,5742 4803.15,4744.09 4507.87,4744.09 4507.87,5000 4606.3,5000 4606.3,5177.17 4370.08,5177.17 4370.08,4980.31 4212.6,4980.31 4212.6,4744.09 3679,4744.09
USB_VBUS on L3-SIG1 "L3_USB_VBUS" (solid, pour order 137): 6230,5594 6018,5594 6018,5518 5716,5518 5716,5106 6230,5106
+VDCIN on L3-SIG1 "L3_+VDCIN" (solid, pour order 112): 270,5492.13 270,3717 2118.36,3717 2299,3897.64 2913.39,3897.64 2913.39,4610.61 2031.87,5492.13
DGND on L3-SIG1 "L3_DGND_1" (solid, pour order 141): 8838.58,5885.83 6358.27,5885.83 6358.27,5255.91 8287.4,5255.91 8425.2,5393.7 8838.58,5393.7
DGND on L3-SIG1 "L3_DGND_3" (solid, pour order 143): 3818.9,4035.43 5492.13,4035.43 5492.13,3149.61 5551.18,3090.55 5551.18,2952.76 5610.24,2893.7 6259.84,2893.7 6574.8,2578.74 7125.98,2578.74 7125.98,1633.86 6240.16,1633.86 4940.94,2933.07 4468.5,2933.07 4468.5,3267.72 3818.9,3917.32
DGND on L3-SIG1 "L3_DGND_4" (solid, pour order 148): 5275.59,19.68 3622.05,19.68 3622.05,866.14 4547.24,866.14 4901.57,1220.47 4980.32,1220.47 5177.17,1023.62 5177.17,314.96 5275.59,216.54
DGND on L3-SIG1 "L3_DGND_6" (solid, pour order 149): 2952.76,3838.58 3208.66,3582.68 3208.66,1791.34 3248.03,1751.97 3248.03,1397.64 4114.17,1397.64 4429.13,1082.68 4645.67,1082.68 4744.09,1181.1 4744.09,1318.9 4429.13,1633.86 4429.13,1909.45 3523.62,2814.96 3523.62,3464.57 3110.24,3877.95 2952.76,3877.95
DGND on L3-SIG1 "L3_DGND_2" (solid, pour order 142): 8838.58,4803.15 7342.52,4803.15 7342.52,1712.6 7637.8,1417.32 8248.03,1417.32 8248.03,807.09 7755.91,807.09 7642.87,694.05 6530.36,694.05 5905.51,1318.9 5649.61,1318.9 5649.61,19.68 8838.58,19.68
DGND on L3-SIG1 "L3_DGND_5" (solid, pour order 147): 19.68,19.68 19.68,1200.79 1574.8,1200.79 1574.8,826.77 2834.65,826.77 3129.92,531.5 3129.92,19.68
VCCO_87_88 on L5-PWR "L5_VCCO_87_88" (solid, pour order 133): 39.37,944.88 216.54,944.88 216.54,1062.99 570.87,1417.32 6082.68,1417.32 7322.84,2657.48 7322.83,3720.47 5334.65,3720.47 4350.39,2736.22 39.37,2736.22
+3.3V_AUX on L5-PWR "L5_+3.3V_AUX" (solid, pour order 114): 39.37,39.37 8818.9,39.37 8818.9,5866.14 39.37,5866.14 39.37,2775.59 4330.71,2775.59 5314.96,3759.84 7362.2,3759.84 7362.2,2637.8 6102.36,1377.95 590.55,1377.95 255.91,1043.31 255.91,905.51 39.37,905.51
+3.3V_QSFP on L6-PWR "L6_+3.3V_QSFP" (solid, pour order 111): 7165.35,4468.5 6673.23,4468.5 6377.95,4173.23 1515.75,4173.23 1515.75,1948.82 6614.17,1948.82 7165.36,2500
+5V_AUX on L6-PWR "L6_+5V_AUX" (solid, pour order 120): 748.03,3877.95 748.03,5393.7 3405.51,5393.7 3661.42,5649.61 3661.42,5866.14 6437.01,5866.14 6437.01,5118.11 5748.03,5118.11 5433.07,5433.07 4173.23,5433.07 3661.42,4921.26 3661.42,4212.6 1476.38,4212.6 1476.38,3877.95
+1.8V_AUX on L6-PWR "L6_+1.8V_AUX" (solid, pour order 116): 1515.75,1909.45 1515.75,708.66 8818.9,708.66 8818.9,5866.14 6476.38,5866.14 6476.38,5078.74 5728.35,5078.74 5424.09,5383 4184,5383 3700.79,4899.79 3700.79,4212.6 6358.27,4212.6 6653.54,4507.87 7204.72,4507.87 7204.72,2480.32 6633.86,1909.45
+5V_SZG on L6-PWR "L6_+5V_SZG" (solid, pour order 119): 8818.9,39.37 8818.9,669.29 1476.38,669.29 1476.38,3838.58 708.66,3838.58 708.66,5433.07 3385.83,5433.07 3622.05,5669.29 3622.05,5866.14 39.37,5866.14 39.37,39.37
AVDDH_KSZ9031 on L10-BOT "L10_AVDDH_KSZ9031" (solid, pour order 122): 4311.02,4842.52 4507.87,4842.52 4507.87,5216.54 4311.02,5216.54
USB_SHELL on L1-TOP "L1_USB_SHELL" (solid, pour order 136): 5834,5581.84 5834,5886.1 6356,5886.1 6356,5581.84 6268.16,5581.84 6250,5600 6250,5710 5947,5710 5947,5601 5927.84,5581.84
+VDCIN on L1-TOP "L1_+VDCIN" (solid, pour order 138): 2811.35,3941.61 2811.35,4215 2390.35,4215 2390.35,3941.61
DGND on L2-GND "L2_DGND" (solid, pour order 115): 19.68,19.68 19.68,5885.83 8838.58,5885.83 8838.58,19.68
DGND on L4-GND "L4_DGND" (solid, pour order 126): 19.68,19.68 19.68,5885.83 8838.58,5885.83 8838.58,19.68
DGND on L9-GND "L9_DGND" (solid, pour order 128): 19.68,19.68 19.68,5885.83 8838.58,5885.83 8838.58,19.68

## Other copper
L1-TOP:
  region net VCCO_67: 1043.71,5865.32 945.71,5865.32 945.71,5777.32 1043.71,5777.32
  rectangle net VCCO_67: 3572,40 3670,128
  region net +3.3V_QSFP_VCCRX2: 6828,3100.18 6828,3147.18 6669,3147.18 6669,3100.18
  region net +3.3V_QSFP_VCCRX1: 6828.01,4316.65 6828.01,4363.65 6669.01,4363.65 6669.01,4316.65
  region net DGND: 5846.94,4868.77 5846.94,4978.77 5823.94,4978.77 5823.94,5035.77 5918.94,5035.77 5918.94,4978.77 5892.94,4978.77 5892.94,4868.77
  region net +3.3V_AUX: 5905.06,4923.77 5943.06,4923.77 5943.06,4942.77 5953.06,4952.77 5982,4952.77 5982,5027.77 5931.62,5027.77 5931.62,4975.45 5923.94,4967.77 5905.06,4967.77
  region net +1.8V_AUX: 5834.94,4923.77 5796.94,4923.77 5796.94,4942.77 5786.94,4952.77 5762.94,4952.77 5762.94,5027.77 5811.94,5027.77 5811.94,4975.77 5819.94,4967.77 5834.94,4967.77
  region net +1.2V_DP: 7332,1054.48 7387,1054.48 7401,1068.48 7572,1068.48 7572,1006.48 7446,1006.48 7446,1023 7429.52,1039.48 7390.48,1039.48 7377,1026 7334.98,1026 7332,1028.98
  region net USB_VBUS: 5793,5365 5793,5330 5787,5324 5787,5302 5735,5302 5735,5365
  region net +5V_AUX: 5793.06,5428.96 5770.06,5428.96 5770.06,5388.96 5703.06,5388.96 5703.06,5494.96 5793.06,5494.96
  region net NetC37_2: 8194.1,520 8343.1,520 8343.1,165 7538.1,165 7538.1,520 7636.1,520 7713.1,443 8117.1,443
  region net NetC211_2: 7209.85,520 7358.85,520 7358.85,165 6553.85,165 6553.85,520 6651.85,520 6728.85,443 7132.85,443
  region net NetC190_2: 2013,520 2162,520 2162,165 1357,165 1357,520 1455,520 1532,443 1936,443
  region net DGND: 7306,979.48 7385.5,979.48 7391.5,973.48 7415,973.48 7434.5,992.98 7570,992.98 7570,936.48 7421,936.48 7414,943.48 7391.5,943.48 7384,935.98 7384,901.48 7393,892.48 7393,795.98 7346,795.98 7346,862.48 7344,864.48 7344,898.24 7357.92,898.24 7367,907.32 7367,933.98 7360.5,940.48 7306,940.48
  region net +3.3V_AUX: 7280.48,954.48 7298,954.48 7298,928.48 7328,898.48 7328,796.42 7271,796.42 7271,945
  region net DGND: 7377,999.48 7312.5,999.48 7306,1005.98 7306,1054.48 7323,1054.48 7323,1018.48 7377,1018.48
  region net +3.3V_QSFP_VCCTX2: 7046.79,2993.17 6977.86,2993.17 6968.36,3002.67 6672.79,3002.67 6672.79,2946.63 6921.77,2946.63 6976.79,2979.67 7046.79,2979.67
  region net +3.3V_QSFP_VCC2: 6908.79,2877.24 6979.79,2948.24 7047.79,2948.24 7047.79,2961.24 6968.79,2961.24 6927.53,2935.24 6672.79,2935.24 6672.79,2877.24
  region net +3.3V_QSFP_VCCTX1: 7046.8,4209.65 6977.87,4209.65 6968.37,4219.14 6672.8,4219.14 6672.8,4163.1 6921.78,4163.1 6976.8,4196.14 7046.8,4196.14
  region net +3.3V_QSFP_VCC1: 6908.8,4093.72 6979.79,4164.72 7047.8,4164.72 7047.8,4177.72 6968.8,4177.72 6927.54,4151.72 6672.8,4151.72 6672.8,4093.72
  region net DGND: 4347,5817.46 4347,5707.46 4370,5707.46 4370,5650.46 4275,5650.46 4275,5707.46 4301,5707.46 4301,5817.46
  region net +1.2V_ETH: 4359,5762.46 4397,5762.46 4397,5743.46 4407,5733.46 4431,5733.46 4431,5658.46 4382,5658.46 4382,5710.46 4374,5718.46 4359,5718.46
  region net +3.3V_AUX: 4288.87,5762.46 4250.87,5762.46 4250.87,5743.46 4240.87,5733.46 4212,5733.46 4212,5658.46 4262.32,5658.46 4262.32,5710.77 4270,5718.46 4288.87,5718.46
  region net +3.3V_AUX: 1597.58,3920.64 1597.58,4260.64 1796.58,4260.64 1796.58,3920.64
  region net NetC126_2: 1422.58,3871.64 1494.58,3871.64 1494.58,3909.64 1508.58,3923.64 1581.58,3923.64 1581.58,4260.64 1494.58,4260.64 1494.58,3966.64 1449.58,3921.64 1422.58,3921.64
  region net DGND: 1383.53,3862.64 1505.58,3862.64 1505.58,3909.64 1590.58,3909.64 1797.58,3909.64 1797.58,3738.64 1589.58,3738.64 1589.58,3832.64 1383.53,3832.64 1383.53,3747.64 1223.58,3747.64 1223.58,3906.64 1383.53,3906.64
  region net +VDCIN: 1422.58,3822.64 1451.58,3822.64 1453.58,3820.64 1575.58,3820.64 1575.58,3745.64 1503.58,3745.64 1456.58,3792.64 1422.58,3792.64
  region net NetC118_2: 1422.58,3783.64 1455.58,3783.64 1502.58,3736.64 1570.58,3736.64 1581.58,3725.64 1581.58,3396.64 1497.58,3396.64 1497.58,3699.64 1488.08,3709.14 1476.08,3709.14 1451.58,3733.64 1422.58,3733.64
  region net +3.3V_QSFP: 1596.58,3726.64 1797.29,3726.64 1797.29,3630.64 1797.29,3396.64 1596.58,3396.64
  region net +VDCIN: 1184.58,3842.64 1184.58,3812.64 1105.58,3812.64 1105.58,3842.64
  region net NetC149_2: 1184.58,3803.64 1015.58,3803.64 1015.58,3394.64 1075.58,3394.64 1075.58,3634.64 1068.58,3634.64 1068.58,3751.64 1108.58,3751.64 1108.58,3784.64 1126.58,3784.64 1134.58,3792.64 1184.58,3792.64
  region net NetC139_2: 1184.58,3862.64 1136.58,3862.64 1125.58,3873.64 1105.58,3873.64 1105.58,3906.64 1066.58,3906.64 1066.58,4021.64 1075.58,4021.64 1075.58,4265.64 1009.58,4265.64 1009.58,4023.64 1015.58,4023.64 1015.58,3851.64 1184.58,3851.64
  region net DGND: 1091.58,3837.64 1004.58,3837.64 1004.58,3902.64 805.58,3902.64 805.58,3761.64 1004.58,3761.64 1004.58,3817.64 1091.58,3817.64
  region net +5V_AUX: 999.58,4265.64 999.58,3917.64 805.29,3917.64 805.29,4018.64 805.29,4265.64
  region net +5V_SZG: 999.58,3395.64 805.29,3395.64 805.29,3648.53 805.29,3746.64 999.58,3746.64
L10-BOT:
  region net DGND: 1397.53,3922.72 1210.53,3922.72 1210.53,3732.72 1397.53,3732.72

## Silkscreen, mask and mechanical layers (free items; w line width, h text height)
Top Overlay:
  lines w4.72: 29.53,4153.54 738.19,4153.54 738.19,4822.83 561.02,4822.83 561.02,5374.02 255.91,5374.02 ; 4862.2,4586.61 1968.5,4586.61 1968.5,1318.9 6377.95,1318.9 6377.95,4586.61 5374.02,4586.61 ; 6911,5623 7213,5623 ; 7358,5622 7501,5622 ; 7386,1377.86 8436,1377.86 ; 7386,2244 8436,2244 ; 255.91,5374.02 29.53,5374.02 255.91,5374.02 ; 1416,1000 1416,1273 2054,1273 2054,1000 1416,1000
  lines w10: 39.67,413.81 472.74,413.81 472.74,2185.46 39.67,2185.46 ; 39.67,2264.2 472.74,2264.2 472.74,4035.86 39.67,4035.86 ; 453.18,5865.84 453.18,5432.77 2224.83,5432.77 2224.83,5865.84 ; 2303.57,5865.84 2303.57,5432.77 4075.23,5432.77 4075.23,5865.84 ; 2326.38,39.37 2326.38,472.44 4294.88,472.44 4294.88,39.37 ; 4373.62,39.37 4373.62,472.44 6342.13,472.44 6342.13,39.37
  lines w10.5: 395,722.9 395,723 ; 396,2572.9 396,2573 ; 408,723 433,723 ; 409,2573 434,2573 ; 445.5,701.5 433,723 ; 445.5,744.5 433,723 ; 446.5,2551.5 434,2573 ; 446.5,2594.5 434,2573 ; 452,690 452,690.1 ; 452,755.5 452,755.6 ; 453,2540 453,2540.1 ; 453,2605.5 453,2605.6 ; 471.4,5507 471.5,5507 ; 482.5,5500.5 504,5488 ; 504,5450 504.1,5450 ; 504,5463 504,5488 ; 525.5,5500.5 504,5488 ; 536.9,5507 537,5507 ; 2322.4,5507 2322.5,5507 ; 2333.5,5500.5 2355,5488 ; 2355,5450 2355.1,5450 ; 2355,5463 2355,5488 ; 2376.5,5500.5 2355,5488 ; 2387.9,5507 2388,5507 ; 3028.34,5516.04 3028.44,5516.04 ; 3039.44,5509.54 3060.94,5497.04 ; 3060.94,5459.04 3061.04,5459.04 ; 3060.94,5472.04 3060.94,5497.04 ; 3082.44,5509.54 3060.94,5497.04 ; 3093.84,5516.04 3093.94,5516.04 ; 3950.4,450 3950.5,450 ; 3961.5,443.5 3983,431 ; 3983,393 3983.1,393 ; 3983,406 3983,431 ; 4004.5,443.5 3983,431 ; 4015.9,450 4016,450 ; 5998.4,451 5998.5,451 ; 6009.5,444.5 6031,432 ; 6031,394 6031.1,394 ; 6031,407 6031,432 ; 6052.5,444.5 6031,432 ; 6063.9,451 6064,451
  text "USB 3.0" at 6421,5885.46 h80 r270
  text "Ethernet" at 4641,5877.57 h80 r270
  text "+1.8V" at 7535,5747 h30 r270
  text "DGND" at 7617,5727 h30 r270
  text "PS CONFIG" at 6863.26,5722 h60
  text "DGND" at 7223,5600 h30
  text "SYZYGY" at 3114.94,5467.04 h40
  text "SYZYGY" at 558,5458 h40
  text "SYZYGY" at 2409,5458 h40
  text "PROG_B" at 6899.61,5413.39 h30 r270
  text "ERROR_OUT" at 6978.35,5413.39 h30 r270
  text "ERROR_STATUS" at 7057.09,5413.39 h30 r270
  text "SRST_B" at 7135.83,5413.39 h30 r270
  text "DONE" at 7214.57,5413.39 h30 r270
  text "MODE3" at 7303.15,5413.39 h30 r270
  text "MODE2" at 7381.89,5413.39 h30 r270
  text "MODE1" at 7460.63,5413.39 h30 r270
  text "MODE0" at 7539.37,5413.39 h30 r270
  text "INIT_B" at 7618.11,5413.39 h30 r270
  text "VDCIN: / +6 to +15 VDC" at 30,5376 h30
  text "SZG PORT C" at 459.5,5316 h80
  text "SZG PORT D" at 2309,5316.33 h80
  text "+1.8V" at 8659,5313 h30
  text "VCCO_67" at 449,5231 h50
  text "VCCO_28" at 2309,5231 h50
  text "TMS" at 8659,5229 h30
  text "JTAG" at 8410,5187.64 h40 r270
  text "TCK" at 8659,5153 h30
  text "I/O BREAKOUT" at 2532.24,5127.95 h40
  text "TDO" at 8659,5072 h30
  text "TDI" at 8659,4997 h30
  text "SRST_B" at 8661,4834 h30
  text "VCCO_68" at 489,4034.83 h50 r270
  text "SZG PORT B" at 582,4034.83 h80 r270
  text "QSFP1" at 6877.72,3672 h80
  text "I/O BREAKOUT" at 1174,2989.35 h40 r270
  text "SYZYGY" at 404,2519 h40 r270
  text "QSFP2" at 6875.39,2454 h80
  text "FPX1301" at 7444.41,2266 h80
  text "SZG PORT A" at 582,2191.62 h78 r270
  text "VCCO_87_88" at 489,2191 h50 r270
  text "'.Part_Number' / '.PCB_Revision'XX" at 5286,760 h40
  text "SYZYGY" at 403,669 h40 r270
  text "DisplayPort / PL SRC" at 6368,630.9 h60 r270
  text "DisplayPort / PS SRC" at 1971,579 h60
  text "SZG PORT E" at 2324.75,578 h80
  text "SZG PORT F" at 4371.94,578 h80
  text "DisplayPort / PL SNK" at 8165,549 h60
  text "VCCO_67" at 2324.75,488 h50
  text "VCCO_28" at 4376.47,488 h50
  text "SATA" at 704,437 h70
  text "SYZYGY" at 6085,402 h40
  text "SYZYGY" at 4037,401 h40
Dimensions:
  text ":::" at 6847,5979 h40 r180
  text ":::" at 2640,5943 h40
  text ":::" at -69,4019 h40 r270
  text ":::" at 8929,3555 h40 r90
  text ":::" at -73,1844 h40 r270
  text ":::" at 8931,1506 h40 r90
  text ":::" at 2528,-62 h40
  text ":::" at 6350,-67 h40
  text "All dimensions in mm unless otherwise specified" at 9247,-80 h50
Outline:
  the board outline again, w7.87
Mechanical:
  lines w3.94: 1968.46,1318.79 1968.46,4586.51 ; 1968.5,1318.9 6377.95,1318.9 6377.95,4586.61 1968.5,4586.61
